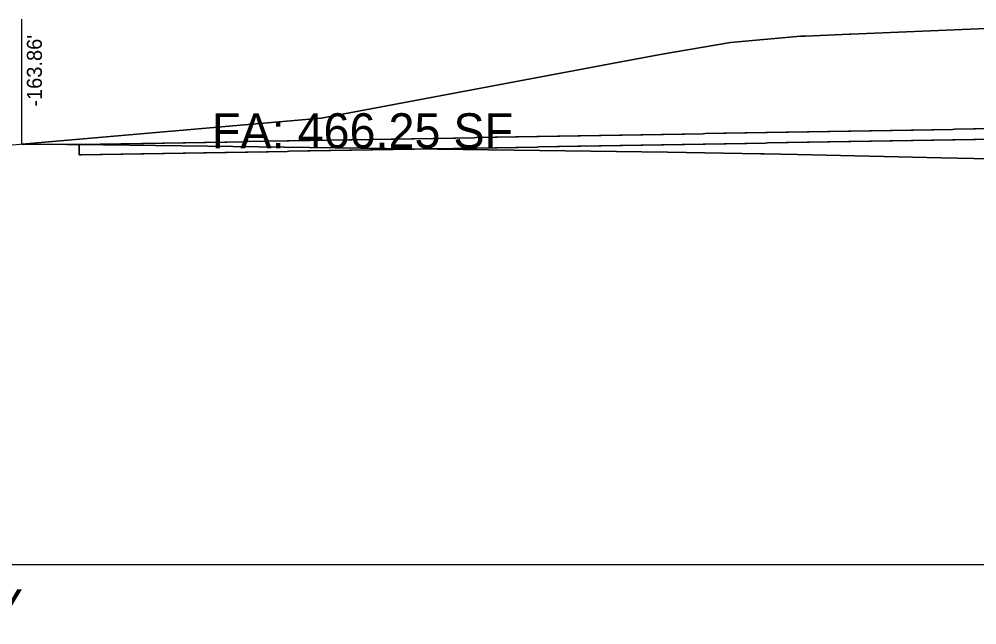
# Model space of a CAD drawing. Extents: x -26 to 4403, y -13 to 9578.
# Drawn here: x 1086.01 to 1132.06, y 997.1 to 1026.2 of the extents above; entities that cross this region are included whole.
import ezdxf

# ---------------------------------------------------------------- set-up
doc = ezdxf.new("R2010")
doc.units = 0
for name, color, linetype in [('CONST_LV3', 7, 'Continuous'), ('DTM_CORRIDOR', 7, 'Continuous'), ('DTM_P_FINISHED_GRADE', 7, 'Continuous'), ('DTM_X_GROUND', 7, 'Continuous'), ('SLOPE_STAKES_FILL', 7, 'Continuous'), ('XS_CELL', 7, 'Continuous'), ('XS_M_SHAPES_EARTHWORK', 7, 'Continuous'), ('XS_P_DR_GRAVEL', 7, 'Continuous'), ('XS_P_GROUND', 7, 'Continuous'), ('XS_P_TX_CLEARZONE', 7, 'Continuous'), ('XS_SHEET_EW_TX_AREA', 7, 'Continuous'), ('XS_SHEET_EW_TX_VOLUME', 7, 'Continuous')]:
    doc.layers.add(name, color=color, linetype=linetype)

msp = doc.modelspace()

# ---------------------------------------------------------------- linework, layer by layer
at = {"layer": 'CONST_LV3'}
msp.add_lwpolyline([(1088.897, 1020.175), (1089, 1020.177), (1089.897, 1020.193), (1090, 1020.194), (1090.897, 1020.21), (1091, 1020.212), (1091.897, 1020.227), (1092, 1020.229), (1092.897, 1020.245), (1093, 1020.247), (1093.897, 1020.262), (1094, 1020.264), (1094.897, 1020.28), (1095, 1020.282), (1095.897, 1020.297), (1096, 1020.299), (1096.897, 1020.315), (1097, 1020.316), (1097.897, 1020.332), (1098, 1020.334), (1098.897, 1020.349), (1099, 1020.351), (1099.897, 1020.367), (1100, 1020.369), (1100.897, 1020.384), (1101, 1020.386), (1101.897, 1020.402), (1102, 1020.404), (1102.897, 1020.419), (1103, 1020.421), (1103.897, 1020.437), (1104, 1020.438), (1104.897, 1020.454), (1105, 1020.456), (1105.897, 1020.472), (1106, 1020.473), (1106.897, 1020.489), (1107, 1020.491), (1107.897, 1020.506), (1108, 1020.508), (1108.897, 1020.524), (1109, 1020.526), (1109.897, 1020.541), (1110, 1020.543), (1110.897, 1020.559), (1111, 1020.56), (1111.897, 1020.576), (1112, 1020.578), (1112.897, 1020.594), (1113, 1020.595), (1113.897, 1020.611), (1114, 1020.613), (1114.897, 1020.628), (1115, 1020.63), (1115.897, 1020.646), (1116, 1020.648), (1116.897, 1020.663), (1117, 1020.665), (1117.897, 1020.681), (1118, 1020.683), (1118.897, 1020.698), (1119, 1020.7), (1119.897, 1020.716), (1120, 1020.717), (1120.897, 1020.733), (1121, 1020.735), (1121.897, 1020.75), (1122, 1020.752), (1122.897, 1020.768), (1123, 1020.77), (1123.897, 1020.785), (1124, 1020.787), (1124.897, 1020.803), (1125, 1020.805), (1125.897, 1020.82), (1126, 1020.822), (1126.897, 1020.838), (1127, 1020.839), (1127.897, 1020.855), (1128, 1020.857), (1128.897, 1020.872), (1129, 1020.874), (1129.897, 1020.89), (1130, 1020.892), (1130.897, 1020.907), (1131, 1020.909), (1131.897, 1020.925), (1132, 1020.927), (1132.897, 1020.942)], dxfattribs=at)
at = {"layer": 'DTM_P_FINISHED_GRADE'}
msp.add_lwpolyline([(1088.897, 1020.175), (1089, 1020.177), (1089.897, 1020.193), (1090, 1020.194), (1090.897, 1020.21), (1091, 1020.212), (1091.897, 1020.227), (1092, 1020.229), (1092.897, 1020.245), (1093, 1020.247), (1093.897, 1020.262), (1094, 1020.264), (1094.897, 1020.28), (1095, 1020.282), (1095.897, 1020.297), (1096, 1020.299), (1096.897, 1020.315), (1097, 1020.316), (1097.897, 1020.332), (1098, 1020.334), (1098.897, 1020.349), (1099, 1020.351), (1099.897, 1020.367), (1100, 1020.369), (1100.897, 1020.384), (1101, 1020.386), (1101.897, 1020.402), (1102, 1020.404), (1102.897, 1020.419), (1103, 1020.421), (1103.897, 1020.437), (1104, 1020.438), (1104.897, 1020.454), (1105, 1020.456), (1105.897, 1020.472), (1106, 1020.473), (1106.897, 1020.489), (1107, 1020.491), (1107.897, 1020.506), (1108, 1020.508), (1108.897, 1020.524), (1109, 1020.526), (1109.897, 1020.541), (1110, 1020.543), (1110.897, 1020.559), (1111, 1020.56), (1111.897, 1020.576), (1112, 1020.578), (1112.897, 1020.594), (1113, 1020.595), (1113.897, 1020.611), (1114, 1020.613), (1114.897, 1020.628), (1115, 1020.63), (1115.897, 1020.646), (1116, 1020.648), (1116.897, 1020.663), (1117, 1020.665), (1117.897, 1020.681), (1118, 1020.683), (1118.897, 1020.698), (1119, 1020.7), (1119.897, 1020.716), (1120, 1020.717), (1120.897, 1020.733), (1121, 1020.735), (1121.897, 1020.75), (1122, 1020.752), (1122.897, 1020.768), (1123, 1020.77), (1123.897, 1020.785), (1124, 1020.787), (1124.897, 1020.803), (1125, 1020.805), (1125.897, 1020.82), (1126, 1020.822), (1126.897, 1020.838), (1127, 1020.839), (1127.897, 1020.855), (1128, 1020.857), (1128.897, 1020.872), (1129, 1020.874), (1129.897, 1020.89), (1130, 1020.892), (1130.897, 1020.907), (1131, 1020.909), (1131.897, 1020.925), (1132, 1020.927), (1132.897, 1020.942)], dxfattribs=at)
at = {"layer": 'DTM_X_GROUND'}
msp.add_lwpolyline([(1084.364, 1020.049), (1100.532, 1021.44), (1114.605, 1024.089), (1116.924, 1024.52), (1120.223, 1025.074), (1123.578, 1025.386), (1123.824, 1025.384), (1125.939, 1025.479), (1126.01, 1025.486), (1135.182, 1025.868), (1142.445, 1025.917), (1146.83, 1025.95), (1147.343, 1025.854), (1148.21, 1025.742), (1149.366, 1025.63), (1164.218, 1020.156), (1164.971, 1019.814), (1182.014, 1017.995), (1182.294, 1017.975), (1182.479, 1017.946), (1182.623, 1017.982), (1200.1, 1016.861), (1205.856, 1017.542), (1237.811, 1018.169)], dxfattribs=at)
at = {"layer": 'XS_CELL'}
msp.add_line((1000, 1000), (1250, 1000), dxfattribs=at)
at = {"layer": 'XS_M_SHAPES_EARTHWORK'}
msp.add_lwpolyline([(1132.897, 1020.442), (1132, 1020.427), (1131.897, 1020.425), (1131, 1020.409), (1130.897, 1020.407), (1130, 1020.392), (1129.897, 1020.39), (1129, 1020.374), (1128.897, 1020.372), (1128, 1020.357), (1127.897, 1020.355), (1127, 1020.339), (1126.897, 1020.338), (1126, 1020.322), (1125.897, 1020.32), (1125, 1020.305), (1124.897, 1020.303), (1124, 1020.287), (1123.897, 1020.285), (1123, 1020.27), (1122.897, 1020.268), (1122, 1020.252), (1121.897, 1020.25), (1121, 1020.235), (1120.897, 1020.233), (1120, 1020.217), (1119.897, 1020.216), (1119, 1020.2), (1118.897, 1020.198), (1118, 1020.183), (1117.897, 1020.181), (1117, 1020.165), (1116.897, 1020.163), (1116, 1020.148), (1115.897, 1020.146), (1115, 1020.13), (1114.897, 1020.128), (1114, 1020.113), (1113.897, 1020.111), (1113, 1020.095), (1112.897, 1020.094), (1112, 1020.078), (1111.897, 1020.076), (1111, 1020.06), (1110.897, 1020.059), (1110, 1020.043), (1109.897, 1020.041), (1109, 1020.026), (1108.897, 1020.024), (1108, 1020.008), (1107.897, 1020.006), (1107, 1019.991), (1106.897, 1019.989), (1106, 1019.973), (1105.897, 1019.972), (1105.472, 1019.964), (1105, 1019.956), (1104.897, 1019.954), (1104, 1019.938), (1103.897, 1019.937), (1103, 1019.921), (1102.897, 1019.919), (1102, 1019.904), (1101.897, 1019.902), (1101, 1019.886), (1100.897, 1019.884), (1100, 1019.869), (1099.897, 1019.867), (1099, 1019.851), (1098.897, 1019.849), (1098, 1019.834), (1097.897, 1019.832), (1097, 1019.816), (1096.897, 1019.815), (1096, 1019.799), (1095.897, 1019.797), (1095, 1019.782), (1094.897, 1019.78), (1094, 1019.764), (1093.897, 1019.762), (1093, 1019.747), (1092.897, 1019.745), (1092, 1019.729), (1091.897, 1019.727), (1091, 1019.712), (1090.897, 1019.71), (1090, 1019.694), (1089.897, 1019.693), (1089, 1019.677), (1088.897, 1019.675), (1088.897, 1020.174), (1088.787, 1020.175), (1088.318, 1020.181), (1086.141, 1020.202), (1100.532, 1021.44), (1114.605, 1024.089), (1116.924, 1024.52), (1120.223, 1025.074), (1123.578, 1025.386), (1123.824, 1025.384), (1125.939, 1025.479), (1126.01, 1025.486), (1135.182, 1025.868)], dxfattribs=at)
at = {"layer": 'XS_P_DR_GRAVEL'}
for points in [[(1132.897, 1020.942), (1132, 1020.927), (1131.897, 1020.925), (1131, 1020.909), (1130.897, 1020.907), (1130, 1020.892), (1129.897, 1020.89), (1129, 1020.874), (1128.897, 1020.872), (1128, 1020.857), (1127.897, 1020.855), (1127, 1020.839), (1126.897, 1020.838), (1126, 1020.822), (1125.897, 1020.82), (1125, 1020.805), (1124.897, 1020.803), (1124, 1020.787), (1123.897, 1020.785), (1123, 1020.77), (1122.897, 1020.768), (1122, 1020.752), (1121.897, 1020.75), (1121, 1020.735), (1120.897, 1020.733), (1120, 1020.717), (1119.897, 1020.716), (1119, 1020.7), (1118.897, 1020.698), (1118, 1020.683), (1117.897, 1020.681), (1117, 1020.665), (1116.897, 1020.663), (1116, 1020.648), (1115.897, 1020.646), (1115, 1020.63), (1114.897, 1020.628), (1114, 1020.613), (1113.897, 1020.611), (1113, 1020.595), (1112.897, 1020.594), (1112, 1020.578), (1111.897, 1020.576), (1111, 1020.56), (1110.897, 1020.559), (1110, 1020.543), (1109.897, 1020.541), (1109, 1020.526), (1108.897, 1020.524), (1108, 1020.508), (1107.897, 1020.506), (1107, 1020.491), (1106.897, 1020.489), (1106, 1020.473), (1105.897, 1020.472), (1105, 1020.456), (1104.897, 1020.454), (1104, 1020.438), (1103.897, 1020.437), (1103, 1020.421), (1102.897, 1020.419), (1102, 1020.404), (1101.897, 1020.402), (1101, 1020.386), (1100.897, 1020.384), (1100, 1020.369), (1099.897, 1020.367), (1099, 1020.351), (1098.897, 1020.349), (1098, 1020.334), (1097.897, 1020.332), (1097, 1020.316), (1096.897, 1020.315), (1096, 1020.299), (1095.897, 1020.297), (1095, 1020.282), (1094.897, 1020.28), (1094, 1020.264), (1093.897, 1020.262), (1093, 1020.247), (1092.897, 1020.245), (1092, 1020.229), (1091.897, 1020.227), (1091, 1020.212), (1090.897, 1020.21), (1090, 1020.194), (1089.897, 1020.193), (1089, 1020.177), (1088.897, 1020.175)], [(1088.897, 1020.175), (1088.897, 1019.675), (1089, 1019.677), (1089.897, 1019.693), (1090, 1019.694), (1090.897, 1019.71), (1091, 1019.712), (1091.897, 1019.727), (1092, 1019.729), (1092.897, 1019.745), (1093, 1019.747), (1093.897, 1019.762), (1094, 1019.764), (1094.897, 1019.78), (1095, 1019.782), (1095.897, 1019.797), (1096, 1019.799), (1096.897, 1019.815), (1097, 1019.816), (1097.897, 1019.832), (1098, 1019.834), (1098.897, 1019.849), (1099, 1019.851), (1099.897, 1019.867), (1100, 1019.869), (1100.897, 1019.884), (1101, 1019.886), (1101.897, 1019.902), (1102, 1019.904), (1102.897, 1019.919), (1103, 1019.921), (1103.897, 1019.937), (1104, 1019.938), (1104.897, 1019.954), (1105, 1019.956), (1105.897, 1019.972), (1106, 1019.973), (1106.897, 1019.989), (1107, 1019.991), (1107.897, 1020.006), (1108, 1020.008), (1108.897, 1020.024), (1109, 1020.026), (1109.897, 1020.041), (1110, 1020.043), (1110.897, 1020.059), (1111, 1020.06), (1111.897, 1020.076), (1112, 1020.078), (1112.897, 1020.094), (1113, 1020.095), (1113.897, 1020.111), (1114, 1020.113), (1114.897, 1020.128), (1115, 1020.13), (1115.897, 1020.146), (1116, 1020.148), (1116.897, 1020.163), (1117, 1020.165), (1117.897, 1020.181), (1118, 1020.183), (1118.897, 1020.198), (1119, 1020.2), (1119.897, 1020.216), (1120, 1020.217), (1120.897, 1020.233), (1121, 1020.235), (1121.897, 1020.25), (1122, 1020.252), (1122.897, 1020.268), (1123, 1020.27), (1123.897, 1020.285), (1124, 1020.287), (1124.897, 1020.303), (1125, 1020.305), (1125.897, 1020.32), (1126, 1020.322), (1126.897, 1020.338), (1127, 1020.339), (1127.897, 1020.355), (1128, 1020.357), (1128.897, 1020.372), (1129, 1020.374), (1129.897, 1020.39), (1130, 1020.392), (1130.897, 1020.407), (1131, 1020.409), (1131.897, 1020.425), (1132, 1020.427), (1132.897, 1020.442)]]:
    msp.add_lwpolyline(points, dxfattribs=at)
at = {"layer": 'XS_P_GROUND'}
for p, q in [((1123.578, 1025.386), (1120.223, 1025.074)), ((1109.897, 1020.541), (1110, 1020.543)), ((1110, 1020.543), (1110.897, 1020.559)), ((1114, 1020.613), (1114.897, 1020.628)), ((1114.897, 1020.628), (1115, 1020.63)), ((1115, 1020.63), (1115.897, 1020.646)), ((1116.897, 1020.663), (1117, 1020.665)), ((1119.897, 1020.716), (1120, 1020.717)), ((1120, 1020.717), (1120.897, 1020.733)), ((1123, 1020.77), (1123.897, 1020.785)), ((1123.897, 1020.785), (1124, 1020.787)), ((1124, 1020.787), (1124.897, 1020.803)), ((1124.897, 1020.803), (1125, 1020.805)), ((1126.897, 1020.838), (1127, 1020.839)), ((1128, 1020.857), (1128.897, 1020.872)), ((1129.897, 1020.89), (1130, 1020.892)), ((1130, 1020.892), (1130.897, 1020.907)), ((1131.897, 1020.925), (1132, 1020.927)), ((1090.897, 1020.21), (1091, 1020.212)), ((1093.897, 1020.262), (1094, 1020.264)), ((1095, 1020.282), (1095.897, 1020.297)), ((1096.897, 1020.315), (1097, 1020.316)), ((1097, 1020.316), (1097.897, 1020.332)), ((1097.897, 1020.332), (1098, 1020.334)), ((1099, 1020.351), (1099.897, 1020.367)), ((1099.897, 1020.367), (1100, 1020.369)), ((1103.897, 1020.437), (1104, 1020.438)), ((1106, 1020.473), (1106.897, 1020.489)), ((1106.897, 1020.489), (1107, 1020.491)), ((1107, 1020.491), (1107.897, 1020.506)), ((1108.897, 1020.524), (1109, 1020.526)), ((1109, 1020.526), (1109.897, 1020.541))]:
    msp.add_line(p, q, dxfattribs=at)
for points in [[(1164.971, 1019.814), (1164.218, 1020.156), (1149.366, 1025.63), (1148.21, 1025.742), (1147.343, 1025.854), (1146.83, 1025.95), (1142.445, 1025.917), (1135.182, 1025.868), (1126.01, 1025.486), (1125.939, 1025.479), (1123.824, 1025.384), (1123.578, 1025.386), (1120.223, 1025.074), (1116.924, 1024.52), (1114.605, 1024.089), (1100.532, 1021.44), (1086.141, 1020.202)], [(1135.182, 1025.868), (1126.01, 1025.486), (1125.939, 1025.479), (1123.824, 1025.384), (1123.578, 1025.386)], [(1120.223, 1025.074), (1116.924, 1024.52), (1114.605, 1024.089), (1100.532, 1021.44), (1086.141, 1020.202)], [(1110.897, 1020.559), (1111, 1020.56), (1111.897, 1020.576)], [(1111.897, 1020.576), (1112, 1020.578), (1112.897, 1020.594), (1113, 1020.595), (1113.897, 1020.611), (1114, 1020.613)], [(1115.897, 1020.646), (1116, 1020.648), (1116.897, 1020.663)], [(1117, 1020.665), (1117.897, 1020.681), (1118, 1020.683), (1118.897, 1020.698)], [(1118.897, 1020.698), (1119, 1020.7), (1119.897, 1020.716)], [(1120.897, 1020.733), (1121, 1020.735), (1121.897, 1020.75)], [(1121.897, 1020.75), (1122, 1020.752), (1122.897, 1020.768), (1123, 1020.77)], [(1125, 1020.805), (1125.897, 1020.82), (1126, 1020.822), (1126.897, 1020.838)], [(1127, 1020.839), (1127.897, 1020.855), (1128, 1020.857)], [(1128.897, 1020.872), (1129, 1020.874), (1129.897, 1020.89)], [(1130.897, 1020.907), (1131, 1020.909), (1131.897, 1020.925)], [(1132, 1020.927), (1132.897, 1020.942), (1133, 1020.944)], [(1179.962, 1018.214), (1179.027, 1018.229), (1172.878, 1018.416), (1171.441, 1018.462), (1167.448, 1018.585), (1150.067, 1019.142), (1130.346, 1019.54), (1123.445, 1019.698), (1121.832, 1019.725), (1121.672, 1019.729), (1117.182, 1019.804), (1093.824, 1020.123), (1088.787, 1020.175), (1088.318, 1020.181), (1086.141, 1020.202)], [(1086.141, 1020.202), (1088.318, 1020.181), (1088.787, 1020.175), (1093.824, 1020.123), (1117.182, 1019.804), (1121.672, 1019.729), (1121.832, 1019.725), (1123.445, 1019.698), (1130.346, 1019.54), (1150.067, 1019.142), (1167.448, 1018.585), (1171.441, 1018.462), (1172.878, 1018.416), (1179.027, 1018.229), (1179.962, 1018.214)], [(1086.141, 1020.202), (1088.318, 1020.181), (1088.787, 1020.175), (1088.897, 1020.174)], [(1088.897, 1020.175), (1089, 1020.177), (1089.897, 1020.193)], [(1088.897, 1020.174), (1088.897, 1020.175)], [(1089.897, 1020.193), (1090, 1020.194), (1090.897, 1020.21)], [(1091, 1020.212), (1091.897, 1020.227), (1092, 1020.229), (1092.897, 1020.245)], [(1092.897, 1020.245), (1093, 1020.247), (1093.897, 1020.262)], [(1094, 1020.264), (1094.897, 1020.28), (1095, 1020.282)], [(1095.897, 1020.297), (1096, 1020.299), (1096.897, 1020.315)], [(1098, 1020.334), (1098.897, 1020.349), (1099, 1020.351)], [(1100, 1020.369), (1100.897, 1020.384), (1101, 1020.386), (1101.897, 1020.402)], [(1101.897, 1020.402), (1102, 1020.404), (1102.897, 1020.419)], [(1102.897, 1020.419), (1103, 1020.421), (1103.897, 1020.437)], [(1104, 1020.438), (1104.897, 1020.454), (1105, 1020.456)], [(1105, 1020.456), (1105.897, 1020.472), (1106, 1020.473)], [(1107.897, 1020.506), (1108, 1020.508), (1108.897, 1020.524)]]:
    msp.add_lwpolyline(points, dxfattribs=at)
at = {"layer": 'XS_P_TX_CLEARZONE'}
msp.add_line((1086.141, 1020.202), (1086.141, 1026.202), dxfattribs=at)
msp.add_line((1086.141, 1020.202), (1086.141, 1026.202), dxfattribs=at)
msp.add_line((1086.141, 1020.202), (1086.141, 1026.202), dxfattribs=at)
msp.add_line((1086.141, 1020.202), (1086.141, 1026.202), dxfattribs=at)
msp.add_line((1086.141, 1020.202), (1086.141, 1026.202), dxfattribs=at)
msp.add_line((1086.141, 1020.202), (1086.141, 1026.202), dxfattribs=at)

# ---------------------------------------------------------------- texts
at = {"layer": 'DTM_CORRIDOR'}
msp.add_text('X', height=0.12, dxfattribs=at).set_placement((1086.102, 1020.142))
at = {"layer": 'SLOPE_STAKES_FILL'}
msp.add_text('X', height=0.12, dxfattribs=at).set_placement((1086.102, 1020.142))
at = {"layer": 'XS_P_TX_CLEARZONE'}
msp.add_text("-163.86'", height=0.72, rotation=90, dxfattribs=at).set_placement((1087.101, 1021.997))
msp.add_text("-163.86'", height=0.72, rotation=90, dxfattribs=at).set_placement((1087.101, 1021.997))
msp.add_text("-163.86'", height=0.72, rotation=90, dxfattribs=at).set_placement((1087.101, 1021.997))
msp.add_text("-163.86'", height=0.72, rotation=90, dxfattribs=at).set_placement((1087.101, 1021.997))
msp.add_text("-163.86'", height=0.72, rotation=90, dxfattribs=at).set_placement((1087.101, 1021.997))
msp.add_text("-163.86'", height=0.72, rotation=90, dxfattribs=at).set_placement((1087.101, 1021.997))
at = {"layer": 'XS_SHEET_EW_TX_AREA'}
msp.add_text('FA: 466.25 SF', height=1.68, dxfattribs=at).set_placement((1095.278, 1020))
at = {"layer": 'XS_SHEET_EW_TX_VOLUME'}
msp.add_text('FV: 401.87 CY', height=1.68, dxfattribs=at).set_placement((1071.457, 997.12))

doc.saveas('drawing.dxf')
